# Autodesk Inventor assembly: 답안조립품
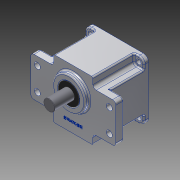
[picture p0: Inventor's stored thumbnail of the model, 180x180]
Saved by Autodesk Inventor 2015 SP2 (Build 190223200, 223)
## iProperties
Created: 2015-06
Part Number: 답안조립품
Document SubType Name: Assembly
Designer: AMC
Author: AMC
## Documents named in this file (12)
- C:\Users\AMC\Desktop\450620V1012\답안조립품.iam
- C:\Users\AMC\Desktop\450620V1012\본체.ipt
- C:\Users\AMC\Desktop\450620V1012\커버.ipt
- C:\Users\AMC\Desktop\450620V1012\베어링 6003.ipt
- 베어링 6003.ipt
- C:\Users\AMC\Desktop\450620V1012\베어링 608.ipt
- 베어링 608.ipt
- C:\Users\AMC\Desktop\450620V1012\오일실 8x22x7.ipt
- C:\Users\AMC\Desktop\450620V1012\오일실 17x32x8.ipt
- C:\Users\AMC\Desktop\450620V1012\서브축.ipt
- C:\Users\AMC\Desktop\450620V1012\메인축.ipt
- C:\Users\AMC\Desktop\450620V1012\M4x0.5x16.ipt
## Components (4 placed, 1 different names)
1. M4x0.5x12:1
2. M4x0.5x12:2
3. M4x0.5x12:3
4. M4x0.5x12:4
